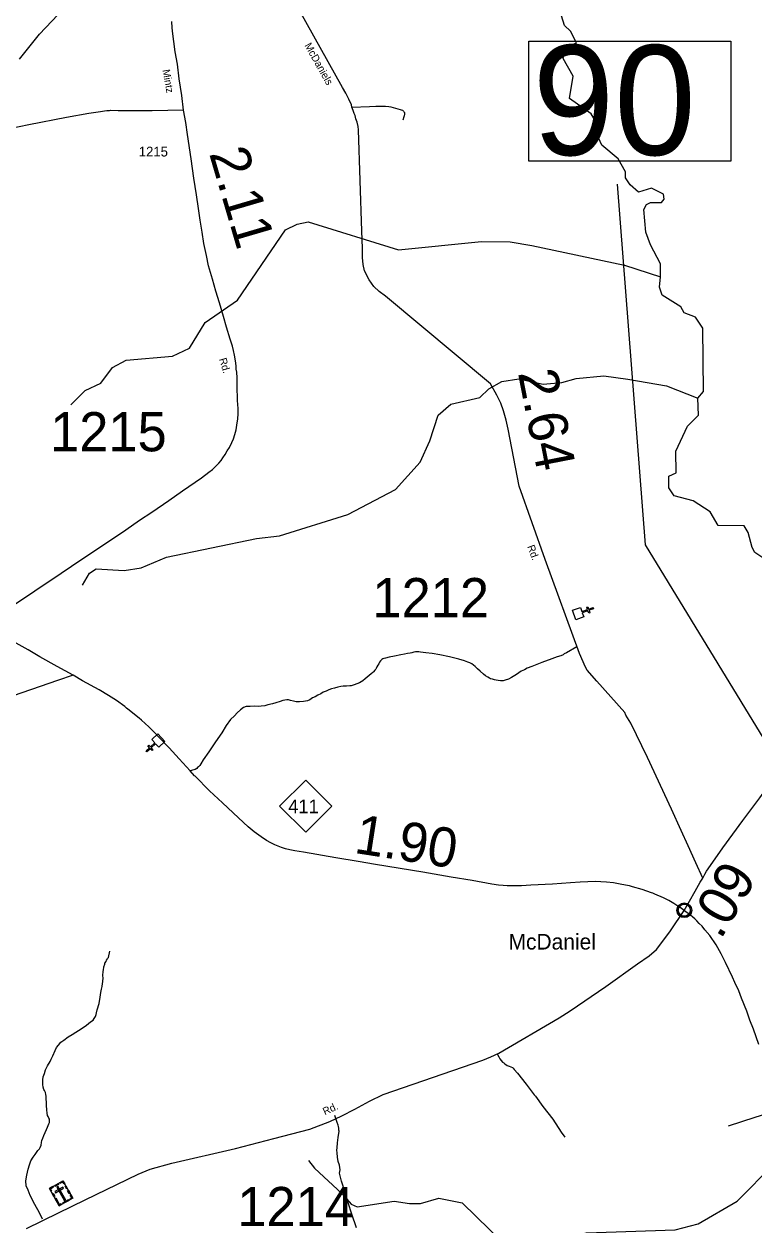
# Model space of a CAD drawing. Extents: x 2093524 to 2270757, y 289120 to 570408.
# Drawn here: x 2157372 to 2166684, y 409015 to 424332 of the extents above; entities that cross this region are included whole.
import ezdxf

# ---------------------------------------------------------------- set-up
doc = ezdxf.new("R2010")
doc.units = 0
for name, color, linetype in [('Exist Civil Demographics Community CELL', 7, 'Continuous'), ('Exist Civil Demographics Community Label', 7, 'Continuous'), ('Exist Cultural Cemetery CELL', 7, 'Continuous'), ('Exist Cultural Church CELL', 7, 'Continuous'), ('Exist Hydrographic Creek Single Shore', 7, 'Continuous'), ('Exist Hydrographic Misc Water Feature', 7, 'Continuous'), ('Exist Road Non-System Type 51', 7, 'Continuous'), ('Exist Road Primary NC Attributed', 7, 'Continuous'), ('Exist Road Primary NC Mileage Hundredths English Label', 7, 'Continuous'), ('Exist Road Primary NC Shield CELL', 7, 'Continuous'), ('Exist Road Primary NC Shield Number Label', 7, 'Continuous'), ('Exist Road Secondary Mileage Hundredths English Label', 7, 'Continuous'), ('Exist Road Secondary Structure Standard Bridge Number Label', 7, 'Continuous'), ('Exist Road Secondary Type 51 Attributed', 7, 'Continuous'), ('Exist Road Secondary Type 51 Label', 7, 'Continuous'), ('Exist Road Secondary Type 51 Number Label', 7, 'Continuous')]:
    doc.layers.add(name, color=color, linetype=linetype)

msp = doc.modelspace()

# ---------------------------------------------------------------- linework, layer by layer
at = {"layer": 'Exist Civil Demographics Community CELL'}
msp.add_lwpolyline([(2165717, 413042), (2165718, 413047), (2165720, 413054), (2165723, 413061), (2165726, 413067), (2165729, 413073), (2165733, 413078), (2165737, 413082), (2165741, 413087), (2165747, 413091), (2165752, 413095), (2165757, 413098), (2165762, 413100), (2165768, 413103), (2165773, 413104), (2165778, 413106), (2165783, 413106), (2165787, 413107), (2165793, 413107), (2165798, 413107), (2165803, 413107), (2165808, 413106), (2165813, 413105), (2165818, 413104), (2165823, 413102), (2165830, 413099), (2165836, 413095), (2165841, 413092), (2165846, 413088), (2165850, 413085), (2165854, 413080), (2165858, 413076), (2165861, 413071), (2165864, 413066), (2165866, 413061), (2165868, 413056), (2165870, 413051), (2165871, 413046), (2165872, 413040), (2165873, 413036), (2165873, 413030), (2165873, 413024), (2165872, 413018), (2165871, 413013), (2165870, 413006), (2165868, 413001), (2165866, 412996), (2165863, 412990), (2165859, 412984), (2165856, 412980), (2165852, 412975), (2165846, 412970), (2165841, 412966), (2165836, 412962), (2165832, 412960), (2165825, 412957), (2165818, 412954), (2165812, 412952), (2165805, 412951), (2165801, 412951), (2165796, 412950), (2165791, 412950), (2165787, 412951), (2165781, 412951), (2165775, 412953), (2165770, 412954), (2165765, 412956), (2165761, 412958), (2165757, 412960), (2165750, 412964), (2165744, 412969), (2165740, 412973), (2165735, 412978), (2165732, 412982), (2165729, 412986), (2165725, 412993), (2165723, 412997), (2165721, 413001), (2165719, 413009), (2165717, 413016), (2165717, 413021), (2165716, 413027), (2165716, 413032), (2165717, 413039)], close=True, dxfattribs=at)
for centre, radius in [((2165795, 413029), 94.3), ((2165795, 413030), 76.7)]:
    msp.add_circle(centre, radius, dxfattribs=at)
at = {"layer": 'Exist Cultural Cemetery CELL'}
for points in [[(2157696, 409480), (2157869, 409578), (2157995, 409357), (2157822, 409258)], [(2157891, 409540), (2157881, 409535), (2157865, 409563), (2157830, 409543), (2157824, 409552), (2157869, 409578)], [(2157718, 409442), (2157727, 409448), (2157711, 409476), (2157747, 409496), (2157741, 409505), (2157696, 409480)], [(2157754, 409378), (2157733, 409415), (2157743, 409421), (2157764, 409383)], [(2157761, 409516), (2157806, 409542), (2157811, 409532), (2157766, 409506)], [(2157765, 409441), (2157774, 409425), (2157877, 409483), (2157868, 409499)], [(2157805, 409508), (2157789, 409499), (2157889, 409323), (2157906, 409332)], [(2157917, 409471), (2157895, 409509), (2157905, 409515), (2157927, 409477)], [(2157949, 409414), (2157928, 409452), (2157938, 409457), (2157959, 409420)], [(2157787, 409319), (2157766, 409357), (2157776, 409362), (2157797, 409325)], [(2157851, 409275), (2157845, 409285), (2157826, 409274), (2157806, 409309), (2157796, 409304), (2157822, 409258)], [(2157866, 409297), (2157940, 409339), (2157946, 409329), (2157872, 409287)], [(2157966, 409340), (2157961, 409350), (2157980, 409361), (2157960, 409396), (2157969, 409402), (2157995, 409357)]]:
    msp.add_lwpolyline(points, close=True, dxfattribs=at)
at = {"layer": 'Exist Cultural Church CELL'}
for points in [[(2164469, 416892), (2164489, 416838), (2164560, 416864), (2164550, 416894), (2164565, 416900), (2164575, 416870), (2164632, 416890), (2164637, 416875), (2164581, 416854), (2164592, 416824), (2164577, 416819), (2164566, 416849), (2164494, 416823), (2164514, 416769), (2164413, 416733), (2164369, 416856)], [(2159090, 415110), (2159051, 415152), (2158995, 415100), (2159017, 415077), (2159005, 415066), (2158984, 415089), (2158940, 415048), (2158929, 415060), (2158973, 415101), (2158951, 415124), (2158963, 415135), (2158984, 415112), (2159040, 415164), (2159001, 415206), (2159079, 415279), (2159168, 415183)]]:
    msp.add_lwpolyline(points, close=True, dxfattribs=at)
at = {"layer": 'Exist Hydrographic Creek Single Shore'}
for points in [[(2165493, 421108), (2165492, 421272), (2165365, 421514), (2165306, 421679), (2165280, 421965), (2165313, 422030), (2165362, 422055), (2165504, 422056), (2165537, 422098), (2165528, 422163), (2165378, 422239), (2165212, 422189), (2165103, 422280), (2165044, 422370), (2165044, 422445), (2164951, 422611), (2164742, 422786), (2164674, 422935), (2164657, 423103), (2164606, 423186), (2164330, 423381), (2164379, 423666), (2164252, 423891), (2164269, 423983), (2164318, 424048), (2164418, 424091), (2164342, 424241), (2164267, 424314), (2164207, 424506)], [(2157971, 419473), (2158153, 419657), (2158353, 419751), (2158502, 419952), (2158676, 420043), (2159267, 420097), (2159483, 420198), (2159681, 420525), (2160096, 420809), (2160708, 421705), (2160857, 421781), (2160999, 421808), (2162150, 421453), (2163208, 421560), (2163574, 421553), (2163849, 421505), (2165034, 421255), (2165493, 421108)], [(2165968, 419560), (2166042, 419644), (2166030, 420451), (2165937, 420594), (2165795, 420649), (2165753, 420725), (2165511, 420875), (2165477, 420974), (2165493, 421108)], [(2166863, 417482), (2166695, 417590), (2166662, 417657), (2166611, 417848), (2166560, 417931), (2166227, 417938), (2166126, 418110), (2165909, 418252), (2165667, 418316), (2165599, 418416), (2165599, 418567), (2165690, 418608), (2165689, 418883), (2165837, 419202), (2165978, 419343), (2165968, 419560)], [(2161002, 409838), (2161077, 409738), (2161429, 409413), (2161546, 409282), (2161621, 409248), (2162096, 409317), (2162288, 409287), (2162429, 409288), (2162662, 409355), (2162962, 409297), (2163490, 408784), (2163657, 408702), (2163915, 408736), (2164547, 408914), (2165680, 408954), (2165971, 409030), (2166469, 409319), (2166941, 409795), (2167164, 409961)]]:
    msp.add_lwpolyline(points, dxfattribs=at)
at = {"layer": 'Exist Hydrographic Misc Water Feature'}
for points in [[(2157313, 423885), (2157570, 424202), (2158042, 424704), (2158224, 424881), (2158332, 424872), (2158533, 424750), (2158649, 424774), (2158716, 424819), (2158889, 425202), (2158962, 425444), (2159045, 425586), (2159319, 425702), (2159477, 425728), (2159802, 425722), (2159952, 425699), (2160377, 425701), (2160786, 425611), (2160986, 425495), (2161530, 424992), (2161624, 424912), (2161740, 424831), (2162131, 424797), (2162955, 424716), (2163685, 424617)], [(2158117, 417174), (2158208, 417327), (2158291, 417384), (2158650, 417360), (2158866, 417396), (2159190, 417530), (2160338, 417770), (2160630, 417806), (2161503, 418078), (2162109, 418397), (2162424, 418742), (2162547, 419015), (2162654, 419341), (2162819, 419485), (2163186, 419569), (2163302, 419679), (2163468, 419771), (2163684, 419806), (2163993, 419740), (2164234, 419759), (2164417, 419811), (2164767, 419846), (2165075, 419804), (2165567, 419716), (2165968, 419560)]]:
    msp.add_lwpolyline(points, dxfattribs=at)
at = {"layer": 'Exist Road Non-System Type 51'}
for points in [[(2159408, 423234), (2159008, 423226), (2158774, 423224), (2158574, 423223), (2158476, 423227), (2158470, 423227), (2158460, 423225), (2158448, 423226), (2158430, 423224), (2158398, 423222), (2158348, 423212), (2158198, 423189), (2157915, 423140), (2157435, 423047), (2157060, 422969), (2156663, 422893)], [(2161555, 423270), (2161779, 423281), (2161861, 423282), (2161985, 423282), (2162024, 423279), (2162053, 423275), (2162169, 423243), (2162185, 423236), (2162201, 423232), (2162215, 423220), (2162219, 423212), (2162225, 423202), (2162227, 423190), (2162227, 423180), (2162223, 423160), (2162217, 423146), (2162205, 423106)], [(2164425, 416390), (2164293, 416310), (2164263, 416298), (2164249, 416288), (2164221, 416275), (2164174, 416263), (2164104, 416237), (2163976, 416190), (2163850, 416139), (2163789, 416115), (2163755, 416097), (2163715, 416077), (2163653, 416036), (2163591, 415996), (2163551, 415974), (2163512, 415962), (2163483, 415953), (2163449, 415955), (2163421, 415961), (2163397, 415963), (2163376, 415967), (2163348, 415977), (2163325, 415980), (2163309, 415988), (2163287, 416000), (2163261, 416018), (2163235, 416038), (2163191, 416080), (2163159, 416110), (2163127, 416139), (2163108, 416155), (2163084, 416173), (2163060, 416185), (2163034, 416195), (2162992, 416212), (2162920, 416230), (2162798, 416261), (2162678, 416285), (2162578, 416302), (2162498, 416312), (2162432, 416321), (2162408, 416323), (2162390, 416325), (2162368, 416325), (2162344, 416319), (2162318, 416313), (2162296, 416309), (2162266, 416302), (2162224, 416296), (2162180, 416286), (2162098, 416270), (2162032, 416255), (2161984, 416245), (2161963, 416239), (2161950, 416235), (2161938, 416226), (2161930, 416220), (2161921, 416208), (2161909, 416192), (2161897, 416172), (2161887, 416154), (2161875, 416132), (2161865, 416114), (2161859, 416104), (2161847, 416090), (2161831, 416070), (2161823, 416060), (2161800, 416046), (2161724, 415981), (2161694, 415955), (2161650, 415931), (2161618, 415915), (2161584, 415903), (2161547, 415892), (2161527, 415892), (2161486, 415888), (2161444, 415886), (2161413, 415882), (2161377, 415876), (2161333, 415863), (2161295, 415853), (2161259, 415841), (2161225, 415825), (2161189, 415810), (2161157, 415790), (2161119, 415772), (2161087, 415752), (2161053, 415738), (2161018, 415713), (2160988, 415701), (2160962, 415697), (2160936, 415691), (2160888, 415689), (2160842, 415686), (2160808, 415694), (2160770, 415702), (2160748, 415712), (2160726, 415712), (2160700, 415708), (2160674, 415704)], [(2157997, 416026), (2157799, 415957), (2157121, 415727)], [(2160674, 415704), (2160640, 415691), (2160584, 415675), (2160540, 415663), (2160484, 415647), (2160442, 415638), (2160398, 415630), (2160360, 415628), (2160306, 415630), (2160258, 415629), (2160232, 415629), (2160207, 415627), (2160170, 415613), (2160133, 415584), (2160089, 415548), (2160055, 415510), (2160007, 415460), (2159952, 415386), (2159894, 415291), (2159815, 415177), (2159728, 415048), (2159659, 414946), (2159627, 414896), (2159613, 414876), (2159599, 414858), (2159585, 414848), (2159575, 414835), (2159555, 414823), (2159539, 414819), (2159491, 414809)], [(2157608, 409091), (2157568, 409171), (2157511, 409277), (2157450, 409392), (2157424, 409458), (2157398, 409514), (2157393, 409576), (2157407, 409650), (2157424, 409726), (2157440, 409784), (2157460, 409832), (2157490, 409878), (2157515, 409914), (2157549, 409964), (2157565, 409980), (2157571, 409986), (2157579, 410004), (2157591, 410034), (2157597, 410066), (2157599, 410092), (2157610, 410124), (2157624, 410156), (2157642, 410194), (2157660, 410232), (2157672, 410262), (2157681, 410284), (2157689, 410305), (2157695, 410322), (2157695, 410341), (2157695, 410364), (2157687, 410376), (2157681, 410399), (2157673, 410412), (2157667, 410442), (2157662, 410482), (2157660, 410540), (2157660, 410582), (2157656, 410620), (2157655, 410658), (2157651, 410680), (2157645, 410704), (2157633, 410730), (2157625, 410744), (2157617, 410774), (2157614, 410806), (2157610, 410830), (2157612, 410866), (2157616, 410906), (2157632, 410948), (2157647, 410994), (2157673, 411046), (2157705, 411098), (2157719, 411130), (2157738, 411171), (2157768, 411240), (2157786, 411279), (2157812, 411309), (2157843, 411345), (2157881, 411373), (2157935, 411414), (2157985, 411444), (2158114, 411525), (2158168, 411565), (2158222, 411605), (2158252, 411629), (2158266, 411649), (2158277, 411663), (2158282, 411673), (2158291, 411701), (2158297, 411721), (2158307, 411761), (2158329, 411841), (2158344, 411921), (2158352, 411978), (2158361, 412024), (2158367, 412056), (2158373, 412094), (2158377, 412114), (2158377, 412134), (2158381, 412154), (2158378, 412204), (2158382, 412240), (2158386, 412278), (2158392, 412294), (2158392, 412306), (2158401, 412342), (2158404, 412354), (2158418, 412374), (2158425, 412392), (2158437, 412408), (2158441, 412416), (2158449, 412428), (2158465, 412506)], [(2163406, 411199), (2163431, 411159), (2163443, 411135), (2163459, 411111), (2163475, 411093), (2163491, 411081), (2163507, 411071), (2163537, 411051), (2163563, 411041), (2163583, 411034), (2163603, 411024), (2163607, 411020), (2163613, 411014), (2163624, 411000), (2163666, 410952), (2163779, 410809), (2163879, 410676), (2163895, 410659), (2163992, 410526), (2164119, 410365), (2164226, 410200), (2164270, 410136)], [(2167051, 410496), (2166696, 410387), (2166356, 410277)], [(2161615, 408980), (2161554, 409151), (2161507, 409299), (2161467, 409429), (2161422, 409572), (2161395, 409674), (2161403, 409720), (2161397, 409776), (2161379, 409826), (2161372, 409880), (2161366, 409937), (2161364, 409971), (2161366, 409999), (2161369, 410063), (2161379, 410129), (2161385, 410159), (2161391, 410206), (2161391, 410213), (2161389, 410226), (2161387, 410250), (2161382, 410271), (2161378, 410289), (2161366, 410323), (2161336, 410413)]]:
    msp.add_lwpolyline(points, dxfattribs=at)
at = {"layer": 'Exist Road Primary NC Attributed'}
for points in [[(2165793, 413027), (2165743, 413065), (2165711, 413083), (2165661, 413115), (2165597, 413152), (2165532, 413188), (2165420, 413235), (2165394, 413245), (2165376, 413249), (2165258, 413292), (2165134, 413328), (2165096, 413339), (2165046, 413347), (2164976, 413361), (2164890, 413378), (2164804, 413388), (2164731, 413393), (2164659, 413397), (2164566, 413390), (2164466, 413386), (2164344, 413377), (2164114, 413362), (2163836, 413348), (2163720, 413340), (2163620, 413339), (2163534, 413340), (2163486, 413346), (2163424, 413350), (2163338, 413361), (2163090, 413410), (2162822, 413452), (2162460, 413516), (2161857, 413611), (2161633, 413652), (2161349, 413696), (2160939, 413768), (2160827, 413785), (2160761, 413801), (2160706, 413814), (2160658, 413828), (2160572, 413862), (2160520, 413887), (2160464, 413917), (2160398, 413965), (2160309, 414028), (2160231, 414094), (2160108, 414207), (2159905, 414398), (2159739, 414553), (2159687, 414604), (2159608, 414686), (2159554, 414739), (2159548, 414744), (2159491, 414809), (2159352, 414960), (2159224, 415102), (2159081, 415249), (2159041, 415293), (2158964, 415368), (2158870, 415455), (2158840, 415479), (2158783, 415527), (2158715, 415579), (2158679, 415608), (2158657, 415626), (2158550, 415702), (2158450, 415767), (2158330, 415838), (2158119, 415955), (2157997, 416026), (2157796, 416139), (2157572, 416262), (2157423, 416349), (2157233, 416458)], [(2166747, 411317), (2166676, 411511), (2166633, 411627), (2166592, 411744), (2166525, 411908), (2166489, 412000), (2166442, 412106), (2166410, 412175), (2166319, 412361), (2166264, 412472), (2166202, 412586), (2166121, 412705), (2166057, 412781), (2166022, 412825), (2165986, 412861), (2165956, 412892), (2165928, 412920), (2165904, 412940), (2165874, 412966), (2165839, 412990), (2165821, 413004), (2165793, 413027)]]:
    msp.add_lwpolyline(points, dxfattribs=at)
at = {"layer": 'Exist Road Primary NC Shield CELL'}
msp.add_lwpolyline([(2160633, 414356), (2160966, 414689), (2161299, 414356), (2160966, 414023)], close=True, dxfattribs=at)
at = {"layer": 'Exist Road Secondary Structure Standard Bridge Number Label'}
msp.add_lwpolyline([(2163810, 424111), (2166387, 424111), (2166387, 422582), (2163810, 422582)], close=True, dxfattribs=at)
msp.add_lwpolyline([(2166814, 415213), (2165300, 417690), (2164942, 422287)], dxfattribs=at)
at = {"layer": 'Exist Road Secondary Type 51 Attributed'}
for points in [[(2166033, 413437), (2165942, 413632), (2165844, 413851), (2165754, 414047), (2165632, 414316), (2165324, 414978), (2165114, 415417), (2165051, 415518), (2165035, 415550), (2164681, 415952), (2164558, 416089), (2164534, 416131), (2164457, 416303), (2164019, 417504), (2163689, 418436), (2163547, 419165), (2163523, 419278), (2163488, 419398), (2163455, 419494), (2163403, 419600), (2163322, 419741), (2161982, 420861), (2161902, 420919), (2161836, 420982), (2161773, 421070), (2161716, 421185), (2161698, 421264), (2161692, 421353), (2161689, 421443), (2161691, 421467), (2161684, 421583), (2161683, 421691), (2161640, 422981), (2161634, 423026), (2161620, 423080), (2161606, 423122), (2161597, 423164), (2161585, 423192), (2161573, 423228), (2161555, 423270), (2161549, 423300), (2161516, 423374), (2161476, 423451), (2161433, 423521), (2160886, 424502)], [(2157135, 416851), (2157511, 417103), (2157845, 417329), (2158109, 417508), (2158411, 417708), (2158672, 417882), (2158845, 418002), (2159003, 418107), (2159220, 418254), (2159395, 418378), (2159636, 418545), (2159730, 418615), (2159777, 418649), (2159795, 418667), (2159823, 418696), (2159857, 418730), (2159887, 418766), (2159907, 418800), (2159940, 418842), (2159964, 418888), (2159992, 418931), (2160021, 418995), (2160043, 419041), (2160063, 419097), (2160078, 419157), (2160088, 419217), (2160098, 419297), (2160103, 419361), (2160103, 419429), (2160096, 419531), (2160093, 419717), (2160089, 419821), (2160085, 419891), (2160080, 419929), (2160078, 419971), (2160070, 420035), (2160059, 420108), (2160043, 420169), (2160032, 420223), (2160002, 420314), (2159957, 420464), (2159916, 420602), (2159865, 420775), (2159821, 420923), (2159776, 421077), (2159725, 421246), (2159700, 421380), (2159667, 421534), (2159646, 421676), (2159620, 421832), (2159597, 421977), (2159572, 422153), (2159538, 422365), (2159503, 422613), (2159457, 422922), (2159437, 423076), (2159408, 423234), (2159385, 423422), (2159353, 423632), (2159328, 423821), (2159302, 423975), (2159285, 424107), (2159270, 424207), (2159262, 424283), (2159257, 424365)], [(2166033, 413437), (2166057, 413489), (2166080, 413529), (2166160, 413643), (2166287, 413824), (2166543, 414174), (2166759, 414461), (2167021, 414834), (2167185, 415066)], [(2165793, 413027), (2165861, 413146), (2165936, 413274), (2165997, 413385), (2166033, 413437)], [(2157402, 408970), (2157810, 409172), (2158154, 409334), (2158828, 409665), (2158981, 409725), (2159258, 409803), (2160071, 409991), (2160561, 410116), (2161019, 410239), (2161273, 410333), (2161426, 410409), (2161591, 410493), (2161781, 410592), (2161954, 410681), (2163227, 411116), (2163329, 411160), (2163428, 411207), (2164198, 411657), (2164339, 411746), (2164795, 412056), (2165197, 412344), (2165349, 412447), (2165440, 412530), (2165498, 412600), (2165619, 412766), (2165793, 413027)]]:
    msp.add_lwpolyline(points, dxfattribs=at)

# ---------------------------------------------------------------- texts
at = {"layer": 'Exist Civil Demographics Community Label'}
msp.add_text('McDaniel', height=200, dxfattribs=at).set_placement((2163553, 412528))
at = {"layer": 'Exist Road Primary NC Mileage Hundredths English Label'}
msp.add_text('1.90', height=500, rotation=351.1251, dxfattribs=at).set_placement((2161571, 413762))
at = {"layer": 'Exist Road Primary NC Shield Number Label'}
msp.add_text('411', height=175, dxfattribs=at).set_placement((2160742, 414266))
at = {"layer": 'Exist Road Secondary Mileage Hundredths English Label'}
for s, rotation, p in [('2.11', 286.3732, (2159731, 422683)), ('2.64', 281.041, (2163672, 419884)), ('.09', 59.583, (2166259, 412644))]:
    msp.add_text(s, height=500, rotation=rotation, dxfattribs=at).set_placement(p)
at = {"layer": 'Exist Road Secondary Structure Standard Bridge Number Label'}
msp.add_text('90', height=1400, dxfattribs=at).set_placement((2163860, 422661))
at = {"layer": 'Exist Road Secondary Type 51 Label'}
for s, rotation, p in [('McDaniels', 299.3136, (2160947, 424059)), ('Mintz', 279.8838, (2159139, 423745)), ('Rd.', 286.7222, (2159860, 420058)), ('Rd.', 290.4638, (2163790, 417668)), ('Rd.', 24.6777, (2161210, 410414))]:
    msp.add_text(s, height=95, rotation=rotation, dxfattribs=at).set_placement(p)
at = {"layer": 'Exist Road Secondary Type 51 Number Label'}
for s, height, p in [('1215', 125, (2158836, 422642)), ('1215', 500, (2157705, 418882)), ('1212', 500, (2161817, 416766)), ('1214', 500, (2160093, 409000))]:
    msp.add_text(s, height=height, dxfattribs=at).set_placement(p)

doc.saveas('drawing.dxf')
